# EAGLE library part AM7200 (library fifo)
FIFO
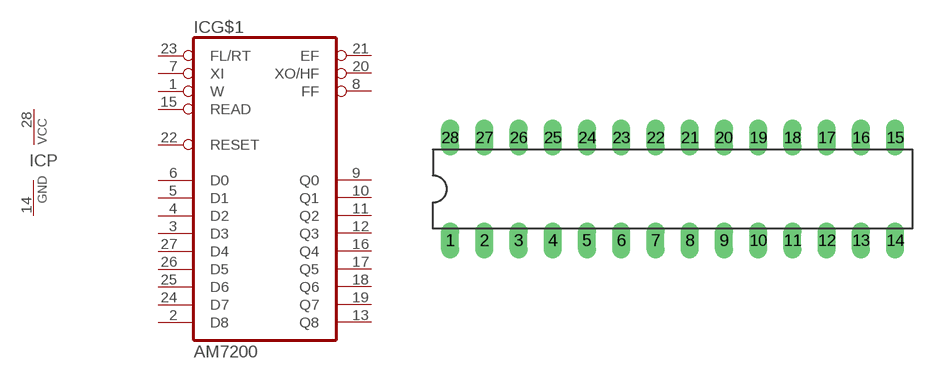
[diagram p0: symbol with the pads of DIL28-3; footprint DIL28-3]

Designator prefix IC; gates G$1=AM7200 P=PWRN

## AM7200 (OC_FARNELL: unknown; OC_NEWARK: unknown)  [DIL28-3]
1  G$1:W  in
2  G$1:D8  in
3  G$1:D3  in
4  G$1:D2  in
5  G$1:D1  in
6  G$1:D0  in
7  G$1:XI  in
8  G$1:FF  out
9  G$1:Q0  out
10  G$1:Q1  out
11  G$1:Q2  out
12  G$1:Q3  out
13  G$1:Q8  out
14  P:GND  pwr
15  G$1:READ  in
16  G$1:Q4  out
17  G$1:Q5  out
18  G$1:Q6  out
19  G$1:Q7  out
20  G$1:XO/HF  out
21  G$1:EF  out
22  G$1:RESET  in
23  G$1:FL/RT  in
24  G$1:D7  in
25  G$1:D6  in
26  G$1:D5  in
27  G$1:D4  in
28  P:VCC  pwr

## Footprint DIL28-3 (pad centres in mm)
Dual In Line Package Small
drill 0.813 long: 1 -16.51,-3.81; 2 -13.97,-3.81; 3 -11.43,-3.81; 4 -8.89,-3.81; 5 -6.35,-3.81; 6 -3.81,-3.81; 7 -1.27,-3.81; 8 1.27,-3.81; 9 3.81,-3.81; 10 6.35,-3.81; 11 8.89,-3.81; 12 11.43,-3.81; 13 13.97,-3.81; 14 16.51,-3.81; 15 16.51,3.81; 16 13.97,3.81; 17 11.43,3.81; 18 8.89,3.81; 19 6.35,3.81; 20 3.81,3.81; 21 1.27,3.81; 22 -1.27,3.81; 23 -3.81,3.81; 24 -6.35,3.81; 25 -8.89,3.81; 26 -11.43,3.81; 27 -13.97,3.81; 28 -16.51,3.81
